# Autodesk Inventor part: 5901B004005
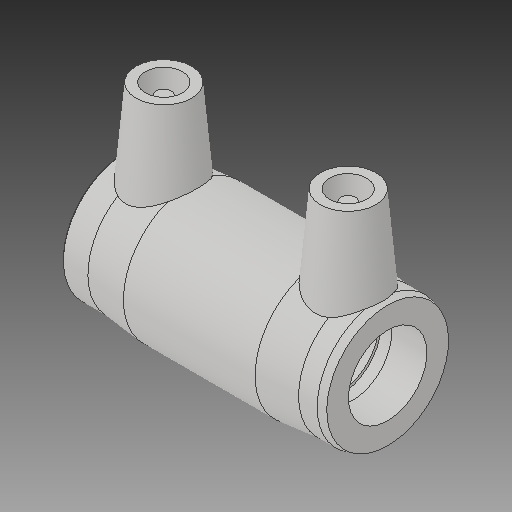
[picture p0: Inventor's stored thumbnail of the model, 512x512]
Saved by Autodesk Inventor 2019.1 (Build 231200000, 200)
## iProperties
Created: 2017-06
Part Number: 5901B004005
Material: Generic
Description: PLASSON IPS COUPLER 1/2''
Document SubType Name: Modeling
Designer: KIM
Mass: 8622.19 g
Surface Area: 6772.47 cm^2
Volume: 8622.19 cm^3
Density: 1 g/cm^3
Appearance: Default
Author: KIM
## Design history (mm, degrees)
derived "5901B.ipt"
feature "Solid1::5901B.ipt"
tag "TaggingFeature1"
body "Solid1"
other parameters: "d0" = 71.12, "d1" = 21.2, "d2" = 36.068, "d3" = 34.544, "d4" = 17.78, "d5" = 32.4612, "d6" = 16.96, "d7" = 21.2, "d8" = 168 deg, "d10" = 13.8176, "d11" = 4.60587, "d13" = 71.12, "d14" = 17.6296, "d18" = 21.2, "d19" = 3.52592, "d20" = 168 deg, "d22" = 33.90392, "d23" = 36.068, "d24" = 32.8868, "d25" = 135 deg, "d26" = 32.004, "d27" = 135 deg, "d29" = 38.354, "d30" = 15, "d31" = 24.892, "d34" = 5 deg, "d35" = 15, "d39" = 5 deg, "d41" = 4, "d42" = 14, "d43" = 0, "d45" = 4, "d46" = 14, "d47" = 0, "d48" = 3, "d49" = 0, "d50" = 3, "d51" = 0, "d52" = 10.01776, "d53" = 2.50444, "d55" = 34.544, "d_" = 21.2, "L_" = 71.12, "L_1" = 34.544, "D_" = 36.068, "A_" = 38.354, "d_2" = 12, "B_" = 38.354
